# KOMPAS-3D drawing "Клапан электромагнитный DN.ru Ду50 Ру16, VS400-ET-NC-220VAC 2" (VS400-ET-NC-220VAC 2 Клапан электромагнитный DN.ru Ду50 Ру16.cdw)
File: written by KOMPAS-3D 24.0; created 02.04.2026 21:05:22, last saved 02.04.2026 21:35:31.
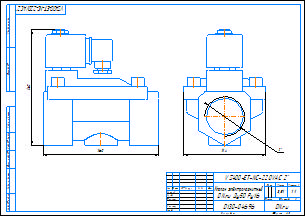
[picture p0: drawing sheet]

Document properties: c3d_UniqueCompID: ef56311e-7521-43dc-8291-0e6108b3d81d; Обозначение: VS400-ET-NC-220VAC 2; Наименование: Клапан электромагнитный DN.ru Ду50 Ру16; Автор: artio; Класс точности: c; Знак неуказанной шероховатости: Шероховатость не задана; Рассекать на разрезах: Да; c3d_UniqueCompID: ef56311e-7521-43dc-8291-0e6108b3d81d; Обозначение: VS400-ET-NC-220VAC 1; Наименование: Клапан электромагнитный DN.ru Ду25 Ру16; Автор: artio; Класс точности: c; Знак неуказанной шероховатости: Шероховатость не задана; Рассекать на разрезах: Да; c3d_UniqueCompID: ef56311e-7521-43dc-8291-0e6108b3d81d; Обозначение: VS400-ET-NC-220VAC 1-2; Наименование: Клапан электромагнитный DN.ru Ду15 Ру16; Автор: artio; Класс точности: c; Знак неуказанной шероховатости: Шероховатость не задана; Рассекать на разрезах: Да; c3d_UniqueCompID: ef56311e-7521-43dc-8291-0e6108b3d81d; Обозначение: VS400-ET-NC-220VAC 3-4; Наименование: Клапан электромагнитный DN.ru Ду20 Ру16; Автор: artio; Класс точности: c; Знак неуказанной шероховатости: Шероховатость не задана; Рассекать на разрезах: Да; c3d_UniqueCompID: ef56311e-7521-43dc-8291-0e6108b3d81d; Обозначение: VS400-ET-NC-220VAC 1 1-4; Наименование: Клапан электромагнитный DN.ru Ду32 Ру16; Автор: artio; Класс точности: c; Знак неуказанной шероховатости: Шероховатость не задана; Рассекать на разрезах: Да; c3d_UniqueCompID: ef56311e-7521-43dc-8291-0e6108b3d81d; Обозначение: VS400-ET-NC-220VAC 3-8; Наименование: Клапан электромагнитный DN.ru Ду10 Ру16; Автор: artio; Класс точности: c; Знак неуказанной шероховатости: Шероховатость не задана; Рассекать на разрезах: Да; c3d_UniqueCompID: ef56311e-7521-43dc-8291-0e6108b3d81d; Обозначение: VS400-ET-NC-220VAC 1 1-2; Наименование: Клапан электромагнитный DN.ru Ду40 Ру16; Автор: artio; Класс точности: c; Знак неуказанной шероховатости: Шероховатость не задана; Рассекать на разрезах: Да; Автор: artio; Форматы листов документа: A3; Полное имя файла: VS400-ET-NC-220VAC 2 Клапан электромагнитный DN.ru Ду50 Ру16.m3d; Масса: 3.509; Наименование: Клапан электромагнитный DN.ru Ду50 Ру16; Количество листов документа: 1; Примечание: D130-04696

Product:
- Body: Тело 1  | qty 1
    Масса: 7.119215
- Part/product: Клапан электромагнитный DN.ru Ду50 Ру16  | designation VS400-ET-NC-220VAC 2
    Масса: 3.509
    Раздел спецификации: Прочие изделия
    Примечание: D130-04696
    additional columns: ef56311e-7521-43dc-8291-0e6108b3d81d; VS400-ET-NC-220VAC 2; artio; c; Шероховатость не задана; Да

Views: Вид 1, Спереди
Referenced files in C:\Users\artio\OneDrive\Рабочий стол\Клапан электромагнитный DN.ru VS4x-xT-NC-x\DN10\: VS400-ET-NC-220VAC 3-8 Клапан электромагнитный DN.ru Ду10 Ру16.m3d, VS400-ET-NC-220VAC 3-8 Клапан электромагнитный DN.ru Ду10 Ру16.cdw
Referenced files in C:\Users\artio\OneDrive\Рабочий стол\Клапан электромагнитный DN.ru VS4x-xT-NC-x\DN50\: VS400-ET-NC-220VAC 2 Клапан электромагнитный DN.ru Ду50 Ру16.m3d
Referenced files in C:\Users\artio\OneDrive\Рабочий стол\Клапан электромагнитный DN.ru\VS400\VS400-ET-NC\VS400-ET-NC-220VAC\Ду50\: VS400-ET-NC-220VAC 2 Клапан электромагнитный DN.ru Ду50 Ру16.m3d
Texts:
  VS400-ET-NC-220VAC 2
  Клапан электромагнитный
  DN.ru Ду50 Ру16
  VS400-ET-NC-220VAC 2"
  VS400-ET-NC-220VAC 2"-
  Клапан электромагнитный DN.ru Ду50 Ру16
  VS400-ET-NC-220VAC 2 Клапан электромагнитный DN.ru Ду50 Ру16
Dimensions and other numbers on the sheet: 0; 3; 2; 4; 114; 1:1; 1; 3,51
